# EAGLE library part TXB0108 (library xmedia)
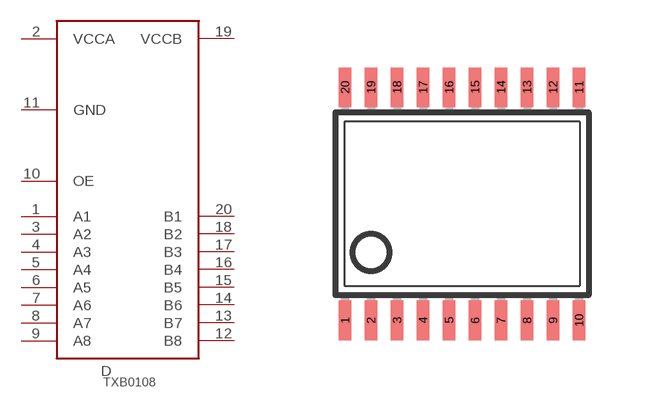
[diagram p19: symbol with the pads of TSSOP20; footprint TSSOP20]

Designator prefix D

## TXB0108  [TSSOP20]
1  A1
2  VCCA  sup
3  A2
4  A3
5  A4
6  A5
7  A6
8  A7
9  A8
10  OE  in
11  GND  sup
12  B8
13  B7
14  B6
15  B5
16  B4
17  B3
18  B2
19  VCCB  sup
20  B1

## Footprint TSSOP20 (pad centres in mm)
Thin Shrink Small Outline Plastic 20 MAX3223-MAX3243.pdf
smd 0.305 x 0.991: 1 -2.925,-2.918; 2 -2.275,-2.918; 3 -1.625,-2.918; 4 -0.975,-2.918; 5 -0.325,-2.918; 6 0.325,-2.918; 7 0.975,-2.918; 8 1.625,-2.918; 9 2.275,-2.918; 10 2.925,-2.918; 11 2.925,2.918; 12 2.275,2.918; 13 1.625,2.918; 14 0.975,2.918; 15 0.325,2.918; 16 -0.325,2.918; 17 -0.975,2.918; 18 -1.625,2.918; 19 -2.275,2.918; 20 -2.925,2.918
